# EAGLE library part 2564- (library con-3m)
3M (TM) Pak 100 4-Wall Header Source: 3M
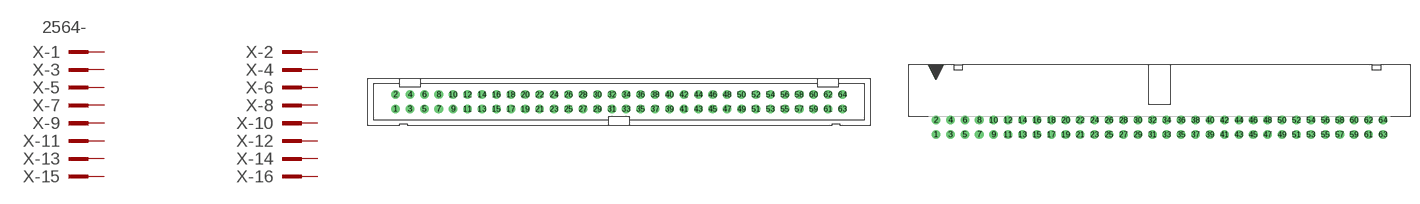
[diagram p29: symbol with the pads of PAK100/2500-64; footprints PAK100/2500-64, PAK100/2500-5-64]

Designator prefix X; gates -1=PINV -2=PIN -3=PIN -4=PIN -5=PIN -6=PIN -7=PIN -8=PIN -9=PIN -10=PIN -11=PIN -12=PIN -13=PIN -14=PIN -15=PIN -16=PIN -17=PIN -18=PIN -19=PIN -20=PIN -21=PIN -22=PIN -23=PIN -24=PIN -25=PIN -26=PIN -27=PIN -28=PIN -29=PIN -30=PIN -31=PIN -32=PIN -33=PIN -34=PIN -35=PIN -36=PIN -37=PIN -38=PIN -39=PIN -40=PIN -41=PIN -42=PIN -43=PIN -44=PIN -45=PIN -46=PIN -47=PIN -48=PIN -49=PIN -50=PIN -51=PIN -52=PIN -53=PIN -54=PIN -55=PIN -56=PIN -57=PIN -58=PIN -59=PIN -60=PIN -61=PIN -62=PIN -63=PIN -64=PIN

## 2564- (OC_FARNELL: unknown; OC_NEWARK: unknown)  [PAK100/2500-64]
1  -1:KL  pas
2  -2:KL  pas
3  -3:KL  pas
4  -4:KL  pas
5  -5:KL  pas
6  -6:KL  pas
7  -7:KL  pas
8  -8:KL  pas
9  -9:KL  pas
10  -10:KL  pas
11  -11:KL  pas
12  -12:KL  pas
13  -13:KL  pas
14  -14:KL  pas
15  -15:KL  pas
16  -16:KL  pas
17  -17:KL  pas
18  -18:KL  pas
19  -19:KL  pas
20  -20:KL  pas
21  -21:KL  pas
22  -22:KL  pas
23  -23:KL  pas
24  -24:KL  pas
25  -25:KL  pas
26  -26:KL  pas
27  -27:KL  pas
28  -28:KL  pas
29  -29:KL  pas
30  -30:KL  pas
31  -31:KL  pas
32  -32:KL  pas
33  -33:KL  pas
34  -34:KL  pas
35  -35:KL  pas
36  -36:KL  pas
37  -37:KL  pas
38  -38:KL  pas
39  -39:KL  pas
40  -40:KL  pas
41  -41:KL  pas
42  -42:KL  pas
43  -43:KL  pas
44  -44:KL  pas
45  -45:KL  pas
46  -46:KL  pas
47  -47:KL  pas
48  -48:KL  pas
49  -49:KL  pas
50  -50:KL  pas
51  -51:KL  pas
52  -52:KL  pas
53  -53:KL  pas
54  -54:KL  pas
55  -55:KL  pas
56  -56:KL  pas
57  -57:KL  pas
58  -58:KL  pas
59  -59:KL  pas
60  -60:KL  pas
61  -61:KL  pas
62  -62:KL  pas
63  -63:KL  pas
64  -64:KL  pas

## 2564-5 (MF: 3M; MPN: N2564-5002RB; OC_FARNELL: unknown; OC_NEWARK: 18M6813)  [PAK100/2500-5-64]
Pads as for PAK100/2500-64

## Footprint PAK100/2500-64 (pad centres in mm)
3M (TM) Pak 100 4-Wall Header Straight Source: 3M
drill 1 pad 1.422 round: 1 -39.37,-1.27; 2 -39.37,1.27; 3 -36.83,-1.27; 4 -36.83,1.27; 5 -34.29,-1.27; 6 -34.29,1.27; 7 -31.75,-1.27; 8 -31.75,1.27; 9 -29.21,-1.27; 10 -29.21,1.27; 11 -26.67,-1.27; 12 -26.67,1.27; 13 -24.13,-1.27; 14 -24.13,1.27; 15 -21.59,-1.27; 16 -21.59,1.27; 17 -19.05,-1.27; 18 -19.05,1.27; 19 -16.51,-1.27; 20 -16.51,1.27; 21 -13.97,-1.27; 22 -13.97,1.27; 23 -11.43,-1.27; 24 -11.43,1.27; 25 -8.89,-1.27; 26 -8.89,1.27; 27 -6.35,-1.27; 28 -6.35,1.27; 29 -3.81,-1.27; 30 -3.81,1.27; 31 -1.27,-1.27; 32 -1.27,1.27; 33 1.27,-1.27; 34 1.27,1.27; 35 3.81,-1.27; 36 3.81,1.27; 37 6.35,-1.27; 38 6.35,1.27; 39 8.89,-1.27; 40 8.89,1.27; 41 11.43,-1.27; 42 11.43,1.27; 43 13.97,-1.27; 44 13.97,1.27; 45 16.51,-1.27; 46 16.51,1.27; 47 19.05,-1.27; 48 19.05,1.27; 49 21.59,-1.27; 50 21.59,1.27; 51 24.13,-1.27; 52 24.13,1.27; 53 26.67,-1.27; 54 26.67,1.27; 55 29.21,-1.27; 56 29.21,1.27; 57 31.75,-1.27; 58 31.75,1.27; 59 34.29,-1.27; 60 34.29,1.27; 61 36.83,-1.27; 62 36.83,1.27; 63 39.37,-1.27; 64 39.37,1.27

## Footprint PAK100/2500-5-64 (pad centres in mm)
3M (TM) Pak 100 4-Wall Header Right Angle Source: 3M
drill 1 pad 1.422 round: 1 -39.37,-1.27; 2 -39.37,1.27; 3 -36.83,-1.27; 4 -36.83,1.27; 5 -34.29,-1.27; 6 -34.29,1.27; 7 -31.75,-1.27; 8 -31.75,1.27; 9 -29.21,-1.27; 10 -29.21,1.27; 11 -26.67,-1.27; 12 -26.67,1.27; 13 -24.13,-1.27; 14 -24.13,1.27; 15 -21.59,-1.27; 16 -21.59,1.27; 17 -19.05,-1.27; 18 -19.05,1.27; 19 -16.51,-1.27; 20 -16.51,1.27; 21 -13.97,-1.27; 22 -13.97,1.27; 23 -11.43,-1.27; 24 -11.43,1.27; 25 -8.89,-1.27; 26 -8.89,1.27; 27 -6.35,-1.27; 28 -6.35,1.27; 29 -3.81,-1.27; 30 -3.81,1.27; 31 -1.27,-1.27; 32 -1.27,1.27; 33 1.27,-1.27; 34 1.27,1.27; 35 3.81,-1.27; 36 3.81,1.27; 37 6.35,-1.27; 38 6.35,1.27; 39 8.89,-1.27; 40 8.89,1.27; 41 11.43,-1.27; 42 11.43,1.27; 43 13.97,-1.27; 44 13.97,1.27; 45 16.51,-1.27; 46 16.51,1.27; 47 19.05,-1.27; 48 19.05,1.27; 49 21.59,-1.27; 50 21.59,1.27; 51 24.13,-1.27; 52 24.13,1.27; 53 26.67,-1.27; 54 26.67,1.27; 55 29.21,-1.27; 56 29.21,1.27; 57 31.75,-1.27; 58 31.75,1.27; 59 34.29,-1.27; 60 34.29,1.27; 61 36.83,-1.27; 62 36.83,1.27; 63 39.37,-1.27; 64 39.37,1.27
